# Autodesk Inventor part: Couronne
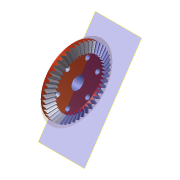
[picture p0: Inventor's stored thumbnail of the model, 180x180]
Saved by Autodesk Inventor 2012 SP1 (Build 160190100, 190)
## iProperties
Created: 2014-12
Part Number: Couronne
Material: Default
Document SubType Name: Modeling
Designer: Bruno
Density: 1 g/cm^3
Mass: 4.64772 g
Surface Area: 44.5223 cm^2
Volume: 4.64772 cm^3
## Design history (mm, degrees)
node "Couronne1"
node "Plan de construction8"
sketch "Esquisse7"
  geometry: L1 (-24.269, -7.937)-(-16.349, -5.551); L2 (4.75, -13.063)-(-4.75, -13.063) reference; L3 (0, -13.063)-(0, -4.631); 1 further point
  constraints: 4 end point, 1 midpoint, 1 perpendicular
  dimensions: "d17" = 73.2357 deg angle of L1 L3 (derived)
feature "SrfRévolution1" sketch "Esquisse7" dims angle "d15" = 90 deg
node "Couronne"
node "Base1"
body "Srf1"
